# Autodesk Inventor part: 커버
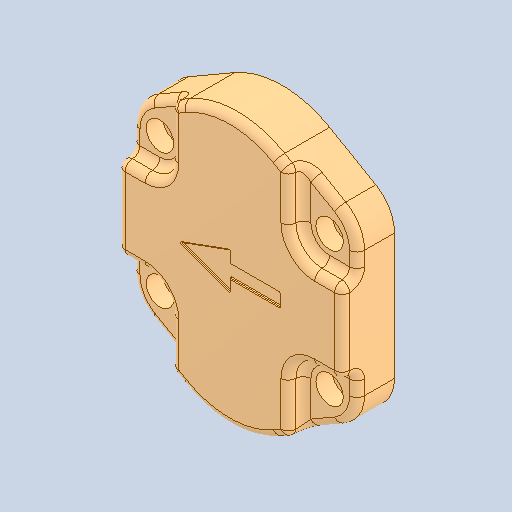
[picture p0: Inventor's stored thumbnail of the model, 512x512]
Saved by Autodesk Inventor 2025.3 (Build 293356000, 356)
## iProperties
Created: 2025-10
Part Number: 커버
Material: 알루미늄 6061
Document SubType Name: Modeling
Designer: PC-15
Density: 2.7 g/cm^3
Appearance: 기본값
Author: jhkim
Sending System: Autodesk Inventor 2026
Preprocessor: ST-DEVELOPER v20.1
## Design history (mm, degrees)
feature "솔리드2"
node "솔리드1"
